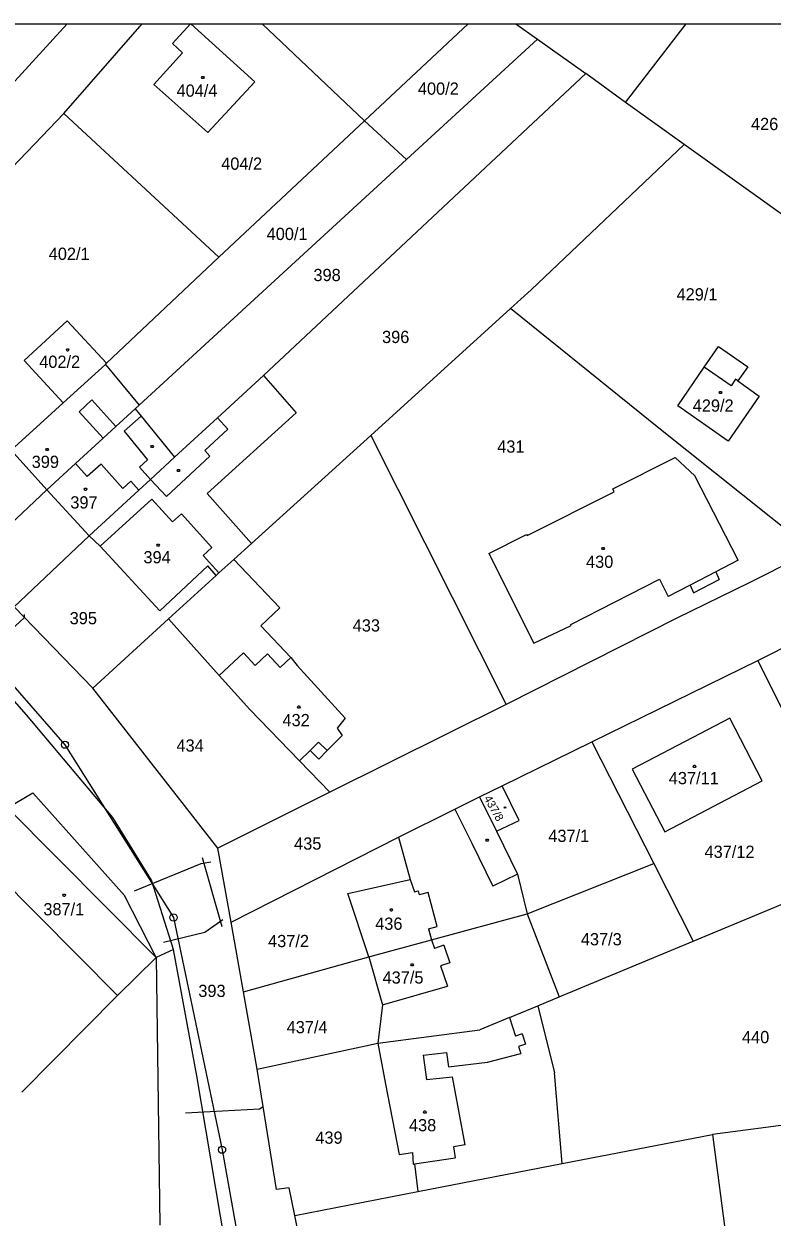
# Model space of a CAD drawing. Extents: x -639621 to -639329, y -1192893 to -1192488.
# Drawn here: x -639535.3 to -639431.2, y -1192653.7 to -1192487.8 of the extents above; entities that cross this region are included whole.
import ezdxf

# ---------------------------------------------------------------- set-up
doc = ezdxf.new("R2010")
doc.units = 0
for name, color, linetype in [('Vrstva 1', 7, 'Continuous'), ('Vrstva 19', 7, 'Continuous'), ('Vrstva 2', 7, 'Continuous'), ('Vrstva 21', 7, 'Continuous'), ('Vrstva 24', 7, 'Continuous'), ('Vrstva 25', 7, 'Continuous'), ('Vrstva 4', 7, 'Continuous'), ('Vrstva 5', 7, 'Continuous'), ('Vrstva 61', 7, 'Continuous')]:
    doc.layers.add(name, color=color, linetype=linetype)

msp = doc.modelspace()

# ---------------------------------------------------------------- linework, layer by layer
at = {"layer": 'Vrstva 1'}
for p, q in [((-639547.5, -1192507.7), (-639529.28, -1192487.83)), ((-639529.73, -1192500.3), (-639518.86, -1192487.83)), ((-639512.13, -1192487.83), (-639514.63, -1192490.58)), ((-639503.19, -1192495.91), (-639512.08, -1192487.83)), ((-639502.15, -1192487.83), (-639487.95, -1192501.33)), ((-639487.95, -1192501.33), (-639473.51, -1192487.83)), ((-639466.87, -1192487.83), (-639463.89, -1192489.96)), ((-639451.66, -1192498.76), (-639443.19, -1192487.83)), ((-639514.63, -1192490.58), (-639513.22, -1192491.87)), ((-639482.08, -1192506.67), (-639463.89, -1192489.96)), ((-639463.89, -1192489.96), (-639457.17, -1192494.75)), ((-639513.22, -1192491.87), (-639517.21, -1192496.27)), ((-639457.17, -1192494.75), (-639502, -1192536.7)), ((-639451.66, -1192498.76), (-639457.17, -1192494.75)), ((-639517.21, -1192496.27), (-639509.7, -1192502.95)), ((-639509.7, -1192502.95), (-639503.19, -1192495.91)), ((-639443.48, -1192504.61), (-639451.66, -1192498.76)), ((-639529.73, -1192500.3), (-639560.27, -1192532.04)), ((-639529.73, -1192500.3), (-639508.19, -1192520.25)), ((-639508.19, -1192520.25), (-639487.95, -1192501.33)), ((-639487.95, -1192501.33), (-639482.08, -1192506.67)), ((-639464.78, -1192524.82), (-639443.48, -1192504.61)), ((-639423.39, -1192518.97), (-639443.48, -1192504.61)), ((-639519.26, -1192540.82), (-639482.08, -1192506.67)), ((-639523.82, -1192535.02), (-639508.19, -1192520.25)), ((-639467.64, -1192527.41), (-639464.78, -1192524.82)), ((-639487.05, -1192545.04), (-639467.64, -1192527.41)), ((-639447, -1192544.01), (-639467.64, -1192527.41)), ((-639535.25, -1192534.61), (-639529.27, -1192529.13)), ((-639529.27, -1192529.13), (-639523.82, -1192535.02)), ((-639440.69, -1192535.56), (-639438.71, -1192532.69)), ((-639438.71, -1192532.69), (-639434.64, -1192535.5)), ((-639529.84, -1192540.49), (-639535.25, -1192534.61)), ((-639529.84, -1192540.49), (-639523.97, -1192535.16)), ((-639523.97, -1192535.16), (-639523.82, -1192535.02)), ((-639523.97, -1192535.16), (-639519.26, -1192540.82)), ((-639502, -1192536.7), (-639508.39, -1192542.59)), ((-639502, -1192536.7), (-639497.45, -1192541.88)), ((-639444.38, -1192540.91), (-639440.69, -1192535.56)), ((-639434.64, -1192535.5), (-639436.03, -1192537.44)), ((-639436.03, -1192537.44), (-639433.06, -1192539.6)), ((-639433.06, -1192539.6), (-639437.36, -1192545.84)), ((-639533.05, -1192543.41), (-639529.84, -1192540.49)), ((-639522.51, -1192543.81), (-639519.83, -1192541.35)), ((-639519.83, -1192541.35), (-639519.26, -1192540.82)), ((-639519.83, -1192541.35), (-639519, -1192542.37)), ((-639509.82, -1192553.1), (-639497.45, -1192541.88)), ((-639437.36, -1192545.84), (-639444.38, -1192540.91)), ((-639537.05, -1192547.08), (-639533.05, -1192543.41)), ((-639519, -1192542.37), (-639514.35, -1192548.08)), ((-639508.39, -1192542.59), (-639511.62, -1192545.56)), ((-639528.1, -1192548.94), (-639524.28, -1192545.43)), ((-639524.28, -1192545.43), (-639522.51, -1192543.81)), ((-639503.65, -1192560.07), (-639487.05, -1192545.04)), ((-639487.05, -1192545.04), (-639468.24, -1192582.43)), ((-639425.67, -1192561.08), (-639447, -1192544.01)), ((-639511.62, -1192545.56), (-639514.35, -1192548.08)), ((-639514.35, -1192548.08), (-639517.68, -1192551.15)), ((-639453.4, -1192552.48), (-639444.72, -1192548.13)), ((-639444.72, -1192548.13), (-639442.02, -1192550.64)), ((-639532.09, -1192552.6), (-639528.1, -1192548.94)), ((-639517.68, -1192551.15), (-639519.32, -1192552.66)), ((-639435.99, -1192562.38), (-639442.02, -1192550.64)), ((-639542.8, -1192562.7), (-639532.09, -1192552.6)), ((-639519.32, -1192552.66), (-639526.21, -1192559.01)), ((-639503.65, -1192560.07), (-639509.82, -1192553.1)), ((-639465.33, -1192558.96), (-639453.2, -1192552.87)), ((-639453.2, -1192552.87), (-639453.4, -1192552.48)), ((-639526.21, -1192559.01), (-639536.67, -1192568.89)), ((-639526.21, -1192559.01), (-639524.7, -1192560.45)), ((-639506.1, -1192562.29), (-639503.65, -1192560.07)), ((-639470.65, -1192561.46), (-639465.4, -1192558.83)), ((-639465.4, -1192558.83), (-639465.33, -1192558.96)), ((-639524.7, -1192560.45), (-639516.41, -1192569.42)), ((-639470.65, -1192561.46), (-639464.4, -1192573.92)), ((-639425.67, -1192561.08), (-639434.43, -1192565.52)), ((-639534.95, -1192583.89), (-639553.16, -1192563.18)), ((-639516.41, -1192569.42), (-639509.74, -1192563.15)), ((-639508.54, -1192564.49), (-639509.74, -1192563.15)), ((-639508.17, -1192564.16), (-639506.1, -1192562.29)), ((-639506.1, -1192562.29), (-639499.72, -1192569.01)), ((-639435.99, -1192562.38), (-639439.1, -1192564)), ((-639515.21, -1192570.53), (-639508.54, -1192564.49)), ((-639508.54, -1192564.49), (-639508.17, -1192564.16)), ((-639459.26, -1192571.32), (-639446.93, -1192565.03)), ((-639446.93, -1192565.03), (-639445.72, -1192567.45)), ((-639442.19, -1192566.9), (-639438.6, -1192565.07)), ((-639439.1, -1192564), (-639438.6, -1192565.07)), ((-639442.65, -1192565.85), (-639445.72, -1192567.45)), ((-639434.43, -1192565.52), (-639444.52, -1192570.43)), ((-639442.65, -1192565.85), (-639442.19, -1192566.9)), ((-639525.7, -1192580.15), (-639536.67, -1192568.89)), ((-639499.72, -1192569.01), (-639502.36, -1192571.52)), ((-639433.26, -1192576.32), (-639418.68, -1192568.97)), ((-639525.7, -1192580.15), (-639515.21, -1192570.53)), ((-639515.21, -1192570.53), (-639508.12, -1192578.42)), ((-639502.36, -1192571.52), (-639498.18, -1192575.92)), ((-639444.52, -1192570.43), (-639468.24, -1192582.43)), ((-639464.4, -1192573.92), (-639459.19, -1192571.46)), ((-639459.19, -1192571.46), (-639459.26, -1192571.32)), ((-639498.18, -1192575.92), (-639497.3, -1192577.02)), ((-639456.32, -1192587.64), (-639433.26, -1192576.32)), ((-639433.26, -1192576.32), (-639426.82, -1192589.24)), ((-639508.12, -1192578.42), (-639503.86, -1192583.16)), ((-639497.3, -1192577.02), (-639490.62, -1192584.36)), ((-639508.34, -1192602.41), (-639525.7, -1192580.15)), ((-639496.96, -1192590.28), (-639503.86, -1192583.16)), ((-639468.24, -1192582.43), (-639492.74, -1192594.64)), ((-639522.94, -1192598.13), (-639534.95, -1192583.89)), ((-639490.62, -1192584.36), (-639491.74, -1192585.74)), ((-639437.15, -1192584.36), (-639450.71, -1192591.45)), ((-639432.62, -1192593.04), (-639437.15, -1192584.36)), ((-639491.04, -1192586.75), (-639493.14, -1192588.86)), ((-639491.74, -1192585.74), (-639491.04, -1192586.75)), ((-639468.8, -1192593.76), (-639456.32, -1192587.64)), ((-639456.32, -1192587.64), (-639447.72, -1192604.54)), ((-639496.96, -1192590.28), (-639495.5, -1192588.82)), ((-639495.5, -1192588.82), (-639494.3, -1192590.02)), ((-639493.14, -1192588.86), (-639494.3, -1192590.02)), ((-639492.74, -1192594.64), (-639496.96, -1192590.28)), ((-639450.71, -1192591.45), (-639446.18, -1192600.12)), ((-639446.18, -1192600.12), (-639432.62, -1192593.04)), ((-639537.59, -1192596.82), (-639534.06, -1192594.73)), ((-639521.3, -1192608.97), (-639534.06, -1192594.73)), ((-639492.74, -1192594.64), (-639508.34, -1192602.41)), ((-639471.92, -1192595.29), (-639468.8, -1192593.76)), ((-639466.43, -1192598.56), (-639468.8, -1192593.76)), ((-639475.35, -1192596.99), (-639471.92, -1192595.29)), ((-639471.92, -1192595.29), (-639469.58, -1192600.06)), ((-639517.56, -1192606.86), (-639522.94, -1192598.13)), ((-639483.2, -1192600.88), (-639475.35, -1192596.99)), ((-639469.58, -1192600.06), (-639466.43, -1192598.56)), ((-639469.58, -1192600.06), (-639466.66, -1192606.02)), ((-639506.47, -1192612.71), (-639483.2, -1192600.88)), ((-639483.2, -1192600.88), (-639481.59, -1192606.77)), ((-639506.47, -1192612.71), (-639508.34, -1192602.41)), ((-639465.33, -1192611.56), (-639447.72, -1192604.54)), ((-639447.72, -1192604.54), (-639442.23, -1192615.33)), ((-639442.23, -1192615.33), (-639417.68, -1192605.12)), ((-639490.24, -1192608.71), (-639481.59, -1192606.77)), ((-639466.66, -1192606.02), (-639465.33, -1192611.56)), ((-639514.49, -1192616.52), (-639517.56, -1192606.86)), ((-639516.92, -1192617.59), (-639521.3, -1192608.97)), ((-639487.35, -1192617.54), (-639490.24, -1192608.71)), ((-639478.6, -1192615.16), (-639465.33, -1192611.56)), ((-639465.33, -1192611.56), (-639460.88, -1192623.08)), ((-639504.77, -1192622.38), (-639506.47, -1192612.71)), ((-639514.49, -1192616.52), (-639516.92, -1192617.59)), ((-639511.27, -1192634.08), (-639514.49, -1192616.52)), ((-639487.35, -1192617.54), (-639478.6, -1192615.16)), ((-639460.88, -1192623.08), (-639442.23, -1192615.33)), ((-639522.28, -1192622.87), (-639516.92, -1192617.59)), ((-639516.92, -1192617.59), (-639516.39, -1192654.83)), ((-639504.77, -1192622.38), (-639487.35, -1192617.54)), ((-639487.35, -1192617.54), (-639485.44, -1192624.21)), ((-639535.58, -1192636.31), (-639522.28, -1192622.87)), ((-639502.88, -1192633.13), (-639504.77, -1192622.38)), ((-639463.84, -1192624.31), (-639460.88, -1192623.08)), ((-639485.44, -1192624.21), (-639486.09, -1192629.51)), ((-639467.76, -1192625.94), (-639463.84, -1192624.31)), ((-639463.84, -1192624.31), (-639461.53, -1192633.63)), ((-639467.76, -1192625.94), (-639471.91, -1192627.67)), ((-639486.09, -1192629.51), (-639471.91, -1192627.67)), ((-639502.88, -1192633.13), (-639486.09, -1192629.51)), ((-639486.09, -1192629.51), (-639484.99, -1192635.2)), ((-639500.18, -1192649.88), (-639502.88, -1192633.13)), ((-639499.71, -1192702.08), (-639511.27, -1192634.08)), ((-639460.43, -1192646.25), (-639461.53, -1192633.63)), ((-639484.99, -1192635.2), (-639483.1, -1192645)), ((-639399.34, -1192636.99), (-639439.54, -1192642.21)), ((-639460.43, -1192646.25), (-639439.54, -1192642.21)), ((-639439.54, -1192642.21), (-639433.22, -1192690.86)), ((-639483.1, -1192645), (-639481.24, -1192644.73)), ((-639481.24, -1192644.73), (-639481.16, -1192646.34)), ((-639481.16, -1192646.34), (-639480.96, -1192646.31)), ((-639480.96, -1192646.31), (-639480.51, -1192650.14)), ((-639480.51, -1192650.14), (-639460.43, -1192646.25)), ((-639498.43, -1192649.61), (-639500.18, -1192649.88)), ((-639497.61, -1192653.45), (-639498.43, -1192649.61)), ((-639497.61, -1192653.45), (-639480.51, -1192650.14)), ((-639490.92, -1192687.58), (-639497.61, -1192653.45))]:
    msp.add_line(p, q, dxfattribs=at)
at = {"layer": 'Vrstva 19'}
msp.add_lwpolyline([(-639583.96, -1192528.01), (-639550.45, -1192564.18), (-639529.58, -1192588.03), (-639514.49, -1192612.05), (-639507.74, -1192644.33), (-639498.83, -1192694.25), (-639511.44, -1192713.33), (-639516.61, -1192716.51), (-639553.94, -1192703.74), (-639570.48, -1192701.62), (-639578.69, -1192703.18)], dxfattribs=at)
for centre in [(-639529.58, -1192588.03), (-639514.49, -1192612.05), (-639507.74, -1192644.33)]:
    msp.add_circle(centre, 0.5, dxfattribs=at)
at = {"layer": 'Vrstva 21'}
msp.add_lwpolyline([(-639510.51, -1192603.73), (-639507.75, -1192613.29)], dxfattribs=at)
at = {"layer": 'Vrstva 24'}
for points in [[(-639544.17, -1192578.16), (-639543.74, -1192578.17), (-639535.21, -1192570.34), (-639535.19, -1192569.92)], [(-639519.93, -1192608.33), (-639510.65, -1192604.54), (-639509.29, -1192604.31)], [(-639512.83, -1192639.19), (-639502.52, -1192638.64), (-639502.03, -1192638.32)]]:
    msp.add_lwpolyline(points, dxfattribs=at)
at = {"layer": 'Vrstva 25'}
for p, q in [((-639507.62, -1192612.39), (-639510.12, -1192614.12)), ((-639510.12, -1192614.12), (-639515.86, -1192615.53))]:
    msp.add_line(p, q, dxfattribs=at)
at = {"layer": 'Vrstva 4'}
for p, q in [((-639436.96, -1192538.13), (-639440.69, -1192535.56)), ((-639436.33, -1192537.22), (-639436.96, -1192538.13)), ((-639436.03, -1192537.44), (-639436.33, -1192537.22)), ((-639527.59, -1192541.75), (-639525.85, -1192540.09)), ((-639525.85, -1192540.09), (-639522.51, -1192543.81)), ((-639527.59, -1192541.75), (-639524.28, -1192545.43)), ((-639519, -1192542.37), (-639521.35, -1192544.47)), ((-639508.39, -1192542.59), (-639506.93, -1192544.18)), ((-639521.35, -1192544.47), (-639518.1, -1192548.42)), ((-639506.93, -1192544.18), (-639510.15, -1192547.15)), ((-639537.05, -1192547.08), (-639532.09, -1192552.6)), ((-639518.1, -1192548.42), (-639519.23, -1192549.47)), ((-639509.42, -1192547.94), (-639515.48, -1192553.53)), ((-639510.15, -1192547.15), (-639509.42, -1192547.94)), ((-639528.1, -1192548.94), (-639526.49, -1192550.74)), ((-639524.56, -1192549.02), (-639526.49, -1192550.74)), ((-639521.53, -1192552.42), (-639524.56, -1192549.02)), ((-639519.23, -1192549.47), (-639517.68, -1192551.15)), ((-639520.42, -1192551.42), (-639521.53, -1192552.42)), ((-639519.32, -1192552.66), (-639520.42, -1192551.42)), ((-639515.48, -1192553.53), (-639517.68, -1192551.15)), ((-639532.09, -1192552.6), (-639526.21, -1192559.01)), ((-639524.7, -1192560.45), (-639517.5, -1192553.89)), ((-639517.5, -1192553.89), (-639514.62, -1192557.05)), ((-639514.62, -1192557.05), (-639513.4, -1192555.94)), ((-639513.4, -1192555.94), (-639509.14, -1192560.6)), ((-639509.14, -1192560.6), (-639510.37, -1192561.73)), ((-639510.37, -1192561.73), (-639508.17, -1192564.16)), ((-639439.1, -1192564), (-639442.65, -1192565.85)), ((-639508.12, -1192578.42), (-639504.77, -1192575.27)), ((-639504.77, -1192575.27), (-639503.13, -1192577.01)), ((-639503.13, -1192577.01), (-639501.44, -1192575.42)), ((-639501.44, -1192575.42), (-639499.66, -1192577.32)), ((-639499.66, -1192577.32), (-639498.18, -1192575.92)), ((-639495.5, -1192588.82), (-639494.34, -1192587.66)), ((-639494.34, -1192587.66), (-639493.14, -1192588.86)), ((-639516.92, -1192617.59), (-639537.59, -1192596.82)), ((-639475.35, -1192596.99), (-639473.02, -1192601.72)), ((-639522.28, -1192622.87), (-639543.41, -1192601.63)), ((-639473.02, -1192601.72), (-639470.07, -1192607.71)), ((-639481.59, -1192606.77), (-639480.98, -1192608.5)), ((-639466.66, -1192606.02), (-639470.07, -1192607.71)), ((-639480.98, -1192608.5), (-639480.46, -1192608.36)), ((-639480.46, -1192608.36), (-639480.31, -1192608.89)), ((-639479.1, -1192608.56), (-639480.31, -1192608.89)), ((-639477.81, -1192613.29), (-639479.1, -1192608.56)), ((-639479.02, -1192613.62), (-639477.81, -1192613.29)), ((-639479.02, -1192613.62), (-639478.6, -1192615.16)), ((-639478.6, -1192615.16), (-639478.2, -1192616.34)), ((-639476.9, -1192615.9), (-639478.2, -1192616.34)), ((-639476.9, -1192615.9), (-639476.08, -1192618.33)), ((-639476.08, -1192618.33), (-639477.38, -1192618.77)), ((-639477.38, -1192618.77), (-639476.41, -1192621.61)), ((-639485.44, -1192624.21), (-639476.41, -1192621.61)), ((-639467.76, -1192625.94), (-639466.95, -1192628.53)), ((-639465.99, -1192628.23), (-639466.95, -1192628.53)), ((-639465.99, -1192628.23), (-639465.55, -1192629.66)), ((-639465.55, -1192629.66), (-639466.5, -1192629.96)), ((-639466.5, -1192629.96), (-639466.19, -1192630.96)), ((-639479.76, -1192631.18), (-639476.55, -1192630.81)), ((-639479.76, -1192631.18), (-639479.3, -1192634.58)), ((-639476.55, -1192630.81), (-639476.24, -1192632.82)), ((-639470.83, -1192632.16), (-639466.19, -1192630.96)), ((-639476.24, -1192632.82), (-639470.83, -1192632.16)), ((-639479.3, -1192634.58), (-639475.69, -1192634.18)), ((-639473.92, -1192643.67), (-639475.69, -1192634.18)), ((-639473.92, -1192643.67), (-639475.57, -1192643.93)), ((-639475.57, -1192643.93), (-639475.34, -1192645.44)), ((-639480.96, -1192646.31), (-639475.34, -1192645.44))]:
    msp.add_line(p, q, dxfattribs=at)
at = {"layer": 'Vrstva 5'}
for points in [[(-639510.33, -1192495.15), (-639510.24, -1192495.3), (-639510.33, -1192495.45), (-639510.51, -1192495.45), (-639510.6, -1192495.3), (-639510.51, -1192495.15)], [(-639529.12, -1192533.01), (-639529.03, -1192533.16), (-639529.12, -1192533.31), (-639529.3, -1192533.31), (-639529.39, -1192533.16), (-639529.3, -1192533.01)], [(-639438.33, -1192538.93), (-639438.24, -1192539.08), (-639438.33, -1192539.23), (-639438.51, -1192539.23), (-639438.6, -1192539.08), (-639438.51, -1192538.93)], [(-639531.98, -1192546.84), (-639531.89, -1192546.99), (-639531.98, -1192547.14), (-639532.16, -1192547.14), (-639532.25, -1192546.99), (-639532.16, -1192546.84)], [(-639517.38, -1192546.44), (-639517.29, -1192546.59), (-639517.38, -1192546.74), (-639517.56, -1192546.74), (-639517.65, -1192546.59), (-639517.56, -1192546.44)], [(-639513.71, -1192549.76), (-639513.62, -1192549.91), (-639513.71, -1192550.06), (-639513.89, -1192550.06), (-639513.98, -1192549.91), (-639513.89, -1192549.76)], [(-639526.64, -1192552.38), (-639526.55, -1192552.53), (-639526.64, -1192552.68), (-639526.82, -1192552.68), (-639526.91, -1192552.53), (-639526.82, -1192552.38)], [(-639516.54, -1192560.14), (-639516.45, -1192560.29), (-639516.54, -1192560.44), (-639516.72, -1192560.44), (-639516.81, -1192560.29), (-639516.72, -1192560.14)], [(-639454.64, -1192560.6), (-639454.55, -1192560.75), (-639454.64, -1192560.9), (-639454.82, -1192560.9), (-639454.91, -1192560.75), (-639454.82, -1192560.6)], [(-639496.99, -1192582.65), (-639496.9, -1192582.8), (-639496.99, -1192582.95), (-639497.17, -1192582.95), (-639497.26, -1192582.8), (-639497.17, -1192582.65)], [(-639441.94, -1192590.89), (-639441.85, -1192591.04), (-639441.94, -1192591.19), (-639442.12, -1192591.19), (-639442.21, -1192591.04), (-639442.12, -1192590.89)], [(-639468.34, -1192596.66), (-639468.28, -1192596.76), (-639468.34, -1192596.86), (-639468.46, -1192596.86), (-639468.52, -1192596.76), (-639468.46, -1192596.66)], [(-639470.79, -1192601.16), (-639470.7, -1192601.31), (-639470.79, -1192601.46), (-639470.97, -1192601.46), (-639471.06, -1192601.31), (-639470.97, -1192601.16)], [(-639529.62, -1192608.81), (-639529.53, -1192608.96), (-639529.62, -1192609.11), (-639529.8, -1192609.11), (-639529.89, -1192608.96), (-639529.8, -1192608.81)], [(-639484.11, -1192610.85), (-639484.02, -1192611), (-639484.11, -1192611.15), (-639484.29, -1192611.15), (-639484.38, -1192611), (-639484.29, -1192610.85)], [(-639481.23, -1192618.47), (-639481.14, -1192618.62), (-639481.23, -1192618.77), (-639481.41, -1192618.77), (-639481.5, -1192618.62), (-639481.41, -1192618.47)], [(-639479.44, -1192638.94), (-639479.35, -1192639.09), (-639479.44, -1192639.24), (-639479.62, -1192639.24), (-639479.71, -1192639.09), (-639479.62, -1192638.94)]]:
    msp.add_lwpolyline(points, close=True, dxfattribs=at)
at = {"layer": 'Vrstva 61'}
msp.add_lwpolyline([(-639621.26, -1192487.83), (-639329.26, -1192487.83)], dxfattribs=at)

# ---------------------------------------------------------------- texts
at = {"layer": 'Vrstva 2'}
for s, p in [('404/4', (-639514.07, -1192497.96)), ('400/2', (-639480.51, -1192497.68)), ('426', (-639434.19, -1192502.6)), ('404/2', (-639507.86, -1192508.11)), ('400/1', (-639501.54, -1192517.88)), ('402/1', (-639531.84, -1192520.64)), ('398', (-639495.03, -1192523.59)), ('429/1', (-639444.54, -1192526.28)), ('396', (-639485.49, -1192532.2)), ('402/2', (-639533.16, -1192535.65)), ('429/2', (-639442.29, -1192541.74)), ('431', (-639469.48, -1192547.44)), ('399', (-639534.21, -1192549.56)), ('397', (-639528.84, -1192555.2)), ('394', (-639518.67, -1192562.82)), ('430', (-639457.13, -1192563.45)), ('395', (-639528.93, -1192571.29)), ('433', (-639489.57, -1192572.3)), ('432', (-639499.34, -1192585.46)), ('434', (-639514.08, -1192588.99)), ('437/11', (-639445.62, -1192593.52)), ('437/1', (-639462.37, -1192601.55)), ('435', (-639497.72, -1192602.62)), ('437/12', (-639440.65, -1192603.76)), ('387/1', (-639532.59, -1192611.75)), ('436', (-639486.45, -1192613.76)), ('437/2', (-639501.34, -1192616.17)), ('437/3', (-639457.85, -1192615.92)), ('437/5', (-639485.42, -1192621.24)), ('393', (-639511.04, -1192623.1)), ('437/4', (-639498.76, -1192628.14)), ('440', (-639435.44, -1192629.52)), ('438', (-639481.75, -1192641.77)), ('439', (-639494.77, -1192643.5))]:
    msp.add_text(s, height=1.7, dxfattribs=at).set_placement(p)
msp.add_text('437/8', height=1.14, rotation=299.3132, dxfattribs=at).set_placement((-639471.37, -1192595.48))

doc.saveas('drawing.dxf')
